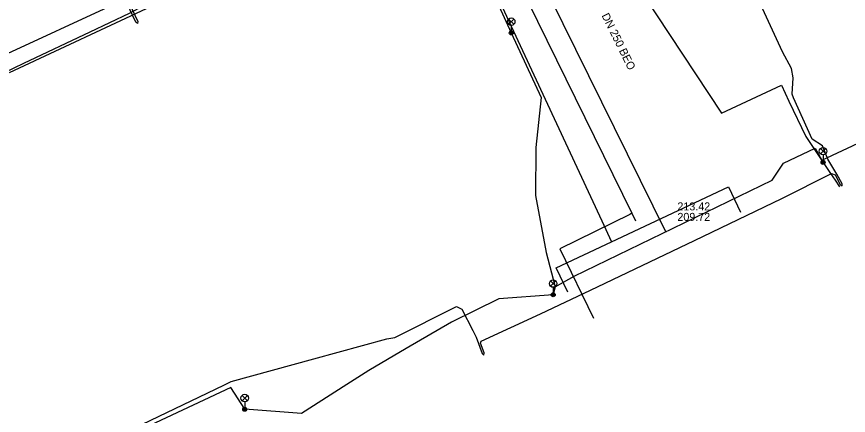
# Model space of a CAD drawing. Extents: x -595540 to -593988, y -1160850 to -1159202.
# Drawn here: x -595488.1 to -595405, y -1160024 to -1159984.1 of the extents above; entities that cross this region are included whole.
import ezdxf

# ---------------------------------------------------------------- set-up
doc = ezdxf.new("R2010")
doc.units = 0
for name, color, linetype in [('BVK-JEDNOTNA_popisy', 7, 'Continuous'), ('BVK-JEDNOTNA_trasa sítě', 7, 'Continuous'), ('BVK-VODOVOD_trasa sítě', 7, 'Continuous'), ('CETIN_kabel podzemní', 7, 'Continuous'), ('DSP-SDEL-VODAFONE_kabel', 7, 'Continuous'), ('EON-NN_kabel', 7, 'Continuous'), ('EON-SDEL_kabel', 7, 'Continuous'), ('INNOGY-NTL_trasa sítě', 7, 'Continuous'), ('QUANTCOM_kabel', 7, 'Continuous'), ('TSB_kabel VO', 7, 'Continuous'), ('TSB_lampy VO', 7, 'Continuous')]:
    doc.layers.add(name, color=color, linetype=linetype)

msp = doc.modelspace()

# ---------------------------------------------------------------- linework, layer by layer
at = {"layer": 'BVK-JEDNOTNA_popisy'}
msp.add_line((-595422.09, -1160003.623), (-595422.09, -1160003.623), dxfattribs=at)
at = {"layer": 'BVK-JEDNOTNA_trasa sítě'}
msp.add_line((-595423.214, -1160005.707), (-595436.668, -1159978.426), dxfattribs=at)
at = {"layer": 'BVK-VODOVOD_trasa sítě'}
for points in [[(-595449.912, -1159956.327), (-595449.568, -1159957.045), (-595442.672, -1159971.097), (-595426.629, -1160003.791), (-595426.262, -1160004.538)], [(-595426.629, -1160003.791), (-595426.855, -1160003.902), (-595433.848, -1160007.334), (-595430.463, -1160014.26)]]:
    msp.add_lwpolyline(points, dxfattribs=at)
at = {"layer": 'CETIN_kabel podzemní'}
for points in [[(-595435.09, -1159963.89), (-595430.67, -1159974.08), (-595417.68, -1159993.79), (-595411.71, -1159990.96), (-595410.95, -1159992.57), (-595409.27, -1159996.12), (-595406.792, -1159999.807)], [(-595488.79, -1159989.71), (-595474.11, -1159982.85)], [(-595487.36, -1159988.78), (-595480.76, -1159985.63), (-595476.81, -1159983.76), (-595475.82, -1159983.24), (-595474.74, -1159982.73)], [(-595489.3, -1159989.71), (-595487.36, -1159988.78)], [(-595406.792, -1159999.807), (-595406.341, -1160000.479)], [(-595406.341, -1160000.479), (-595405.89, -1160001.15)]]:
    msp.add_lwpolyline(points, dxfattribs=at)
at = {"layer": 'DSP-SDEL-VODAFONE_kabel'}
msp.add_lwpolyline([(-595508.68, -1159991.34), (-595508.07, -1159991.03), (-595507.3, -1159990.66), (-595503.44, -1159988.48), (-595499.73, -1159986.66), (-595498.89, -1159986.53), (-595498.42, -1159986.89), (-595498.17, -1159987.35), (-595495.61, -1159992.03), (-595495.16, -1159992.13), (-595494.56, -1159991.94), (-595490.1, -1159990.03), (-595489.3, -1159989.71), (-595487.362, -1159988.784), (-595480.76, -1159985.63), (-595476.81, -1159983.76), (-595475.82, -1159983.24), (-595474.74, -1159982.73)], dxfattribs=at)
at = {"layer": 'EON-NN_kabel'}
for points in [[(-595478.027, -1159980.281), (-595476.001, -1159984.615), (-595476.02, -1159984.81), (-595476.191, -1159984.681), (-595478.193, -1159980.399)], [(-595476.35, -1160025.26), (-595467.41, -1160020.96), (-595466.68, -1160020.6), (-595458.42, -1160018.34), (-595451.11, -1160016.34), (-595450.31, -1160016.21), (-595444.14, -1160013.11), (-595443.61, -1160013.37), (-595442.53, -1160015.52), (-595442.188, -1160016.181), (-595441.583, -1160017.807), (-595441.42, -1160017.96), (-595441.396, -1160017.738), (-595441.756, -1160016.769), (-595441.68, -1160016.57), (-595435.77, -1160013.84), (-595430.76, -1160011.49), (-595420.37, -1160006.5), (-595411.67, -1160002.32), (-595406.71, -1159999.8), (-595406.338, -1159999.957), (-595405.821, -1160000.923), (-595405.648, -1160001.034), (-595405.639, -1160000.838), (-595406.162, -1159999.863), (-595407.05, -1159998.38), (-595407.6, -1159997.03), (-595408.64, -1159996.36), (-595410.5, -1159992.25), (-595410.64, -1159991.86), (-595410.54, -1159990.24), (-595410.7, -1159989.3), (-595411.6, -1159987.64), (-595414.79, -1159980.67)]]:
    msp.add_lwpolyline(points, dxfattribs=at)
at = {"layer": 'EON-SDEL_kabel'}
msp.add_lwpolyline([(-595490.33, -1159988.411), (-595477.63, -1159982.541), (-595476.4, -1159981.991), (-595466.6, -1159976.821), (-595451.16, -1159969.721), (-595450.19, -1159969.131), (-595447.2, -1159967.861), (-595445.4, -1159967.071), (-595441.56, -1159965.511)], dxfattribs=at)
at = {"layer": 'INNOGY-NTL_trasa sítě'}
for points in [[(-595459.42, -1159952.03), (-595450.02, -1159960.712), (-595429.637, -1160004.55)], [(-595428.667, -1160006.636), (-595416.992, -1160001.148), (-595415.803, -1160003.672)], [(-595429.637, -1160004.55), (-595428.667, -1160006.636)], [(-595433.041, -1160011.675), (-595434.189, -1160009.226), (-595428.667, -1160006.636)]]:
    msp.add_lwpolyline(points, dxfattribs=at)
at = {"layer": 'QUANTCOM_kabel'}
msp.add_lwpolyline([(-595490.33, -1159988.41), (-595477.63, -1159982.54), (-595476.4, -1159981.99), (-595466.6, -1159976.82), (-595451.16, -1159969.72), (-595450.19, -1159969.13), (-595447.2, -1159967.86), (-595445.4, -1159967.07), (-595441.56, -1159965.51), (-595433.7, -1159961.55), (-595426.19, -1159958.04), (-595425.02, -1159957.56), (-595414.07, -1159952.36), (-595398.55, -1159944.79)], dxfattribs=at)
at = {"layer": 'TSB_kabel VO'}
for points in [[(-595454.11, -1159961.8), (-595456.04, -1159957.89), (-595455.41, -1159957.66), (-595449.28, -1159959.9), (-595448.33, -1159961.7), (-595445.4, -1159969.13), (-595445.34, -1159971.12), (-595438.7, -1159985.73), (-595435.7, -1159992.2), (-595436.24, -1159997.2), (-595436.25, -1160002), (-595435.21, -1160007.7), (-595434.29, -1160011.13), (-595434.5, -1160011.94)], [(-595407.66, -1159998.48), (-595381.327, -1159986.14), (-595381.12, -1159986.44)], [(-595434.5, -1160011.94), (-595434.29, -1160011.13), (-595432.4, -1160010.06), (-595412.64, -1160000.49), (-595411.51, -1159998.77), (-595408.32, -1159997.27), (-595407.66, -1159998.48)], [(-595434.5, -1160011.94), (-595439.92, -1160012.34), (-595444.66, -1160014.69), (-595449.17, -1160017.32), (-595452.91, -1160019.52), (-595455.1, -1160020.9), (-595459.65, -1160023.82), (-595465.31, -1160023.39)], [(-595465.31, -1160023.39), (-595466.684, -1160021.198), (-595495.214, -1160034.586), (-595495.734, -1160035.103)]]:
    msp.add_lwpolyline(points, dxfattribs=at)
at = {"layer": 'TSB_lampy VO'}
for p, q in [((-595438.955, -1159984.89), (-595438.425, -1159984.36)), ((-595438.955, -1159984.36), (-595438.425, -1159984.89)), ((-595438.955, -1159984.89), (-595438.425, -1159984.36)), ((-595438.955, -1159984.36), (-595438.425, -1159984.89)), ((-595438.69, -1159985), (-595438.69, -1159985.75)), ((-595438.69, -1159985), (-595438.69, -1159985.75)), ((-595407.805, -1159997.84), (-595407.275, -1159997.31)), ((-595407.805, -1159997.31), (-595407.275, -1159997.84)), ((-595407.805, -1159997.84), (-595407.275, -1159997.31)), ((-595407.805, -1159997.31), (-595407.275, -1159997.84)), ((-595407.54, -1159997.95), (-595407.54, -1159998.7)), ((-595407.54, -1159997.95), (-595407.54, -1159998.7)), ((-595434.765, -1160011.08), (-595434.235, -1160010.55)), ((-595434.765, -1160010.55), (-595434.235, -1160011.08)), ((-595434.765, -1160011.08), (-595434.235, -1160010.55)), ((-595434.765, -1160010.55), (-595434.235, -1160011.08)), ((-595434.5, -1160011.19), (-595434.5, -1160011.94)), ((-595434.5, -1160011.19), (-595434.5, -1160011.94)), ((-595465.575, -1160022.53), (-595465.045, -1160022)), ((-595465.575, -1160022), (-595465.045, -1160022.53)), ((-595465.575, -1160022.53), (-595465.045, -1160022)), ((-595465.575, -1160022), (-595465.045, -1160022.53)), ((-595465.31, -1160022.64), (-595465.31, -1160023.39)), ((-595465.31, -1160022.64), (-595465.31, -1160023.39))]:
    msp.add_line(p, q, dxfattribs=at)
for centre, radius in [((-595438.69, -1159984.625), 0.375), ((-595438.69, -1159984.625), 0.375), ((-595438.69, -1159985.75), 0.2), ((-595438.69, -1159985.75), 0.2), ((-595438.69, -1159985.75), 0.145), ((-595438.69, -1159985.75), 0.145), ((-595438.69, -1159985.75), 0.0876), ((-595438.69, -1159985.75), 0.0876), ((-595407.54, -1159997.575), 0.375), ((-595407.54, -1159997.575), 0.375), ((-595407.54, -1159998.7), 0.2), ((-595407.54, -1159998.7), 0.2), ((-595407.54, -1159998.7), 0.145), ((-595407.54, -1159998.7), 0.145), ((-595407.54, -1159998.7), 0.0876), ((-595407.54, -1159998.7), 0.0876), ((-595434.5, -1160010.815), 0.375), ((-595434.5, -1160010.815), 0.375), ((-595434.5, -1160011.94), 0.2), ((-595434.5, -1160011.94), 0.2), ((-595434.5, -1160011.94), 0.145), ((-595434.5, -1160011.94), 0.145), ((-595434.5, -1160011.94), 0.0876), ((-595434.5, -1160011.94), 0.0876), ((-595465.31, -1160022.265), 0.375), ((-595465.31, -1160022.265), 0.375), ((-595465.31, -1160023.39), 0.2), ((-595465.31, -1160023.39), 0.2), ((-595465.31, -1160023.39), 0.145), ((-595465.31, -1160023.39), 0.145), ((-595465.31, -1160023.39), 0.0876), ((-595465.31, -1160023.39), 0.0876)]:
    msp.add_circle(centre, radius, dxfattribs=at)

# ---------------------------------------------------------------- texts
at = {"layer": 'BVK-JEDNOTNA_popisy'}
msp.add_text('DN 250 BEO', height=0.8, rotation=296.28169, dxfattribs=at).set_placement((-595429.687, -1159984.009))
for s, p in [('213.42', (-595422.09, -1160003.498)), ('209.72', (-595422.09, -1160004.548))]:
    msp.add_text(s, height=0.8, dxfattribs=at).set_placement(p)

doc.saveas('drawing.dxf')
